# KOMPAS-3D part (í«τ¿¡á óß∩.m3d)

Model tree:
1. Эскиз:1
2. Операция выдавливания:1
     Расстояние 1 = 2
3. Эскиз:2
4. Операция выдавливания:2
     Расстояние 1 = 4.5
5. Эскиз:3
6. Операция выдавливания:3
     Расстояние 1 = 2
7. Эскиз:4
8. Операция выдавливания:4
     Расстояние 1 = 78
9. Эскиз:5
10. Операция выдавливания:5
     Расстояние 1 = 2
11. Эскиз:6
12. Операция выдавливания:6
     Расстояние 1 = 4.5
13. Эскиз:7
14. Операция выдавливания:7
     Расстояние 1 = 2
15. Скругление:1
     Радиус = 1
16. Скругление:2
     Радиус = 1
17. Эскиз:8
18. Вырезать элемент выдавливания:1
     Расстояние 1 = 10; Угол 1 = 35
19. Эскиз:9
20. Вырезать элемент выдавливания:2
     Расстояние 1 = 10; Угол 1 = 35
21. Эскиз:10
22. Вырезать элемент выдавливания:3
     Расстояние 2 = 22; Расстояние 1 = 22; Угол 1 = 35
23. Эскиз:11
24. Вырезать элемент выдавливания:4
     Расстояние 2 = 2; Расстояние 1 = 2
25. Эскиз:12
26. Вырезать элемент выдавливания:5
     Расстояние 2 = 2; Расстояние 1 = 2; Угол 1 = 35
